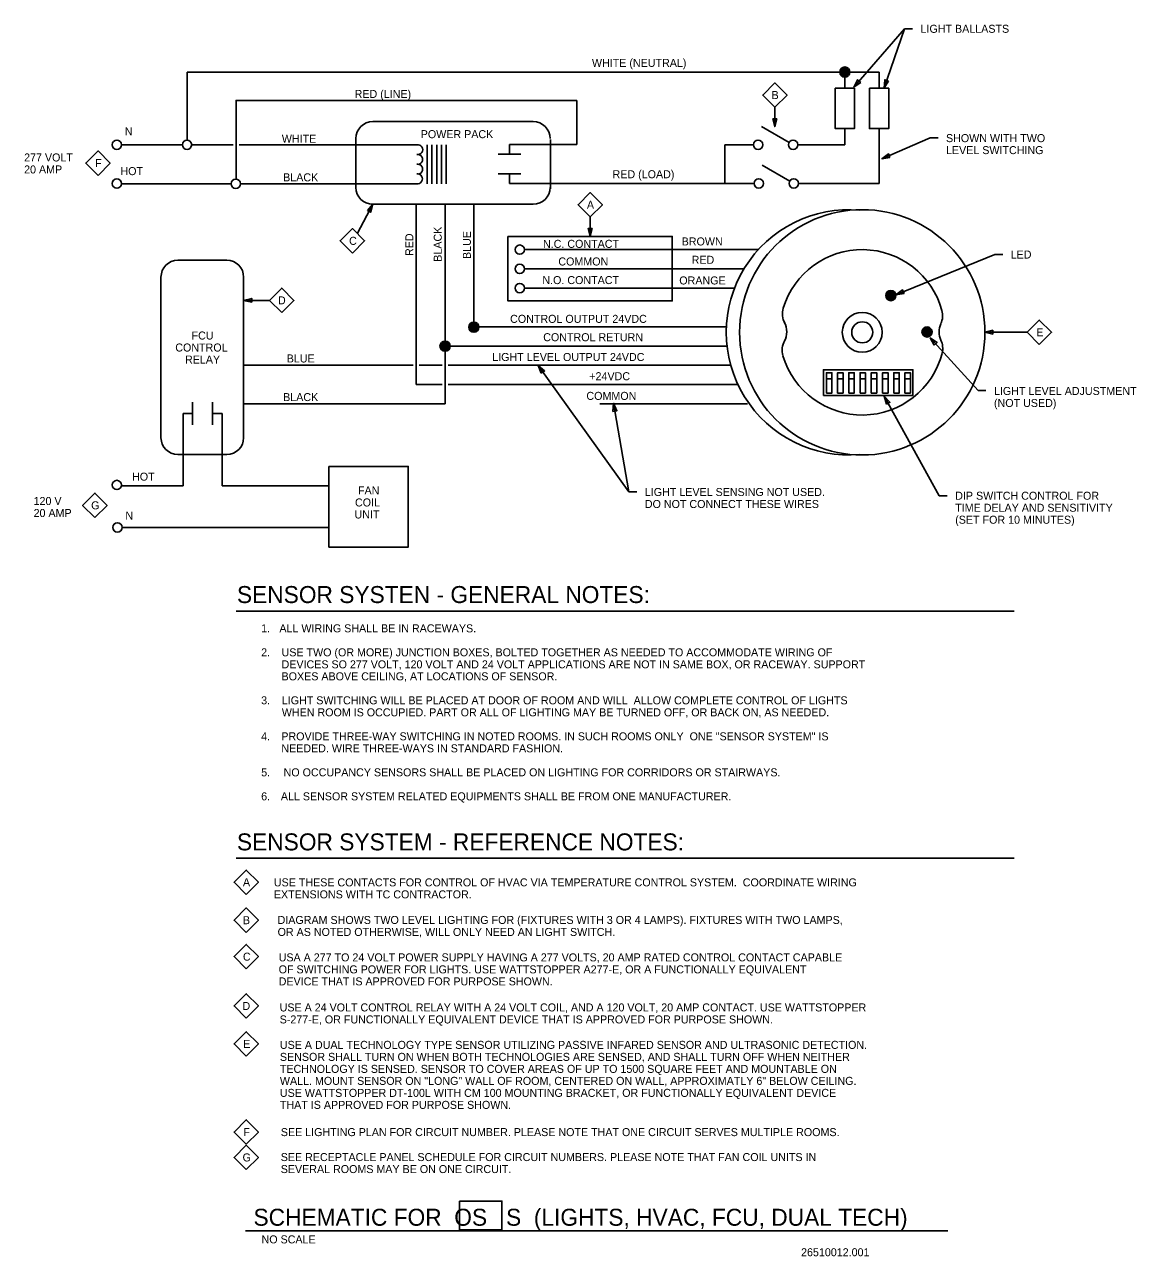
# Model space of a CAD drawing. Extents: x 10087 to 10180, y 10043 to 10146.
import ezdxf

# ---------------------------------------------------------------- set-up
doc = ezdxf.new("R2010")
doc.units = 0
for name, color, linetype in [('G-ANNO-TEXT', 7, 'Continuous'), ('G-DETL-LINE', 7, 'Continuous'), ('G-DETL-OTLN', 7, 'Continuous')]:
    doc.layers.add(name, color=color, linetype=linetype)

msp = doc.modelspace()

# ---------------------------------------------------------------- linework, layer by layer
at = {"layer": 'G-ANNO-TEXT'}
for p, q in [((10160.22, 10145.71), (10156, 10140.85)), ((10160.22, 10145.71), (10158.52, 10140.77)), ((10160.89, 10145.71), (10160.22, 10145.71)), ((10160.89, 10145.71), (10160.22, 10145.71)), ((10149.41, 10139.16), (10149.41, 10137.54)), ((10162.35, 10136.62), (10158.34, 10134.88)), ((10163.02, 10136.62), (10162.35, 10136.62)), ((10115.9, 10131.08), (10114.64, 10128.67)), ((10134.02, 10130.03), (10134.02, 10128.4)), ((10167.74, 10126.89), (10159.51, 10123.54)), ((10168.41, 10126.89), (10167.74, 10126.89)), ((10107.3, 10123.07), (10105.14, 10123.07)), ((10170.45, 10120.41), (10166.91, 10120.41)), ((10166.35, 10115.55), (10162.37, 10119.95)), ((10137.24, 10107.13), (10129.7, 10117.64)), ((10167.01, 10115.55), (10166.35, 10115.55)), ((10137.24, 10107.13), (10135.97, 10114.5)), ((10163.12, 10106.79), (10158.53, 10115.08)), ((10137.91, 10107.13), (10137.24, 10107.13)), ((10137.91, 10107.13), (10137.24, 10107.13)), ((10163.79, 10106.79), (10163.12, 10106.79)), ((10104.51, 10097.18), (10169.35, 10097.18)), ((10104.51, 10076.58), (10169.35, 10076.58)), ((10105.28, 10045.53), (10163.82, 10045.53))]:
    msp.add_line(p, q, dxfattribs=at)
for points in [[(10149.41, 10139.16), (10148.4, 10140.18), (10149.41, 10141.2), (10150.43, 10140.18)], [(10156.57, 10141.24), (10156, 10140.85), (10156.31, 10141.46)], [(10158.9, 10141.35), (10158.52, 10140.77), (10158.58, 10141.46)], [(10149.58, 10138.2), (10149.41, 10137.54), (10149.25, 10138.2)], [(10093, 10133.49), (10091.98, 10134.51), (10093, 10135.53), (10094.01, 10134.51)], [(10159.01, 10134.99), (10158.34, 10134.88), (10158.88, 10135.29)], [(10134.02, 10130.03), (10133.01, 10131.04), (10134.02, 10132.06), (10135.04, 10131.04)], [(10115.45, 10130.57), (10115.9, 10131.08), (10115.74, 10130.42)], [(10114.2, 10127.02), (10113.18, 10128.04), (10114.2, 10129.05), (10115.22, 10128.04)], [(10134.19, 10129.07), (10134.02, 10128.4), (10133.86, 10129.07)], [(10108.31, 10122.06), (10107.3, 10123.07), (10108.31, 10124.09), (10109.33, 10123.07)], [(10160.19, 10123.64), (10159.51, 10123.54), (10160.06, 10123.94)], [(10105.81, 10122.91), (10105.14, 10123.07), (10105.81, 10123.24)], [(10167.58, 10120.25), (10166.91, 10120.41), (10167.58, 10120.58)], [(10171.46, 10119.4), (10170.45, 10120.41), (10171.46, 10121.43), (10172.48, 10120.41)], [(10162.69, 10119.34), (10162.37, 10119.95), (10162.94, 10119.57)], [(10129.95, 10117), (10129.7, 10117.64), (10130.22, 10117.2)], [(10135.92, 10113.82), (10135.97, 10114.5), (10136.25, 10113.88)], [(10158.71, 10114.42), (10158.53, 10115.08), (10159, 10114.58)], [(10092.74, 10104.97), (10091.72, 10105.99), (10092.74, 10107.01), (10093.75, 10105.99)], [(10105.35, 10073.57), (10104.34, 10074.58), (10105.35, 10075.6), (10106.37, 10074.58)], [(10105.35, 10070.41), (10104.34, 10071.42), (10105.35, 10072.44), (10106.37, 10071.42)], [(10105.35, 10067.37), (10104.34, 10068.39), (10105.35, 10069.4), (10106.37, 10068.39)], [(10105.35, 10063.26), (10104.34, 10064.28), (10105.35, 10065.29), (10106.37, 10064.28)], [(10105.35, 10060.1), (10104.34, 10061.11), (10105.35, 10062.13), (10106.37, 10061.11)], [(10105.35, 10052.75), (10104.34, 10053.77), (10105.35, 10054.79), (10106.37, 10053.77)], [(10105.35, 10050.64), (10104.34, 10051.66), (10105.35, 10052.67), (10106.37, 10051.66)], [(10123.12, 10048.01), (10126.67, 10048.01), (10126.67, 10045.62), (10123.12, 10045.62)]]:
    msp.add_lwpolyline(points, close=True, dxfattribs=at)
at = {"layer": 'G-DETL-LINE'}
for p, q in [((10100.42, 10136.43), (10100.42, 10142.1)), ((10158.11, 10142.1), (10100.42, 10142.1)), ((10155.25, 10142.1), (10155.25, 10140.75)), ((10158.11, 10142.1), (10158.11, 10140.75)), ((10132.92, 10136.07), (10132.92, 10139.74)), ((10155.25, 10137.39), (10155.25, 10136.04)), ((10158.11, 10137.39), (10158.11, 10132.82)), ((10094.96, 10136.04), (10100.04, 10136.04)), ((10100.81, 10136.04), (10104.26, 10136.04)), ((10104.76, 10136.04), (10119.58, 10136.03)), ((10120.43, 10136.03), (10120.43, 10132.79)), ((10120.83, 10136.03), (10120.83, 10132.79)), ((10121.23, 10136.03), (10121.23, 10132.79)), ((10121.63, 10136.03), (10121.63, 10132.79)), ((10122.03, 10136.03), (10122.03, 10132.79)), ((10127.3, 10136.07), (10132.92, 10136.07)), ((10127.3, 10136.07), (10127.3, 10135.26)), ((10145.24, 10132.82), (10145.24, 10136.04)), ((10145.24, 10136.04), (10147.66, 10136.04)), ((10155.25, 10136.04), (10151.33, 10136.04)), ((10126.36, 10135.26), (10128.25, 10135.26)), ((10094.96, 10132.79), (10104.09, 10132.79)), ((10104.87, 10132.79), (10119.56, 10132.79)), ((10126.36, 10133.62), (10128.25, 10133.62)), ((10127.3, 10132.82), (10127.3, 10133.62)), ((10127.3, 10132.82), (10147.61, 10132.82)), ((10158.11, 10132.82), (10151.38, 10132.82)), ((10119.53, 10116.06), (10119.53, 10131.08)), ((10121.93, 10114.46), (10121.93, 10131.08)), ((10124.33, 10120.86), (10124.33, 10131.08)), ((10148.05, 10127.3), (10128.54, 10127.3)), ((10146.85, 10125.7), (10128.54, 10125.7)), ((10146.07, 10124.1), (10128.54, 10124.1)), ((10145.39, 10120.86), (10124.33, 10120.86)), ((10145.44, 10119.26), (10121.93, 10119.26)), ((10119.28, 10117.66), (10105.14, 10117.66)), ((10121.68, 10117.66), (10119.78, 10117.66)), ((10145.75, 10117.66), (10122.18, 10117.66)), ((10153.71, 10116.54), (10154.17, 10116.54)), ((10154.64, 10116.54), (10155.1, 10116.54)), ((10155.58, 10116.54), (10156.04, 10116.54)), ((10156.52, 10116.54), (10156.97, 10116.54)), ((10157.45, 10116.54), (10157.91, 10116.54)), ((10158.39, 10116.54), (10158.85, 10116.54)), ((10159.32, 10116.54), (10159.78, 10116.54)), ((10160.26, 10116.54), (10160.72, 10116.54)), ((10121.68, 10116.06), (10119.53, 10116.06)), ((10146.35, 10116.06), (10122.18, 10116.06)), ((10100.89, 10112.7), (10100.89, 10114.58)), ((10102.53, 10112.7), (10102.53, 10114.58)), ((10121.93, 10114.46), (10105.14, 10114.46)), ((10147.14, 10114.46), (10134.82, 10114.46)), ((10100.09, 10113.64), (10100.09, 10107.62)), ((10100.09, 10113.64), (10100.89, 10113.64)), ((10103.34, 10113.64), (10102.53, 10113.64)), ((10103.34, 10113.64), (10103.34, 10107.62)), ((10100.09, 10107.62), (10094.96, 10107.62)), ((10112.24, 10107.62), (10103.34, 10107.62))]:
    msp.add_line(p, q, dxfattribs=at)
for points in [[(10132.92, 10139.74), (10104.51, 10139.74), (10104.51, 10133.18)], [(10112.24, 10104.15), (10095.01, 10104.15)]]:
    msp.add_lwpolyline(points, dxfattribs=at)
for points in [[(10127.17, 10128.4), (10140.87, 10128.4), (10140.87, 10123.03), (10127.17, 10123.03)], [(10153.47, 10115.15), (10160.92, 10115.15), (10160.92, 10117.29), (10153.47, 10117.29)], [(10153.71, 10115.35), (10154.17, 10115.35), (10154.17, 10117.04), (10153.71, 10117.04)], [(10154.64, 10115.35), (10155.1, 10115.35), (10155.1, 10117.04), (10154.64, 10117.04)], [(10155.58, 10115.35), (10156.04, 10115.35), (10156.04, 10117.04), (10155.58, 10117.04)], [(10156.52, 10115.35), (10156.97, 10115.35), (10156.97, 10117.04), (10156.52, 10117.04)], [(10157.45, 10115.35), (10157.91, 10115.35), (10157.91, 10117.04), (10157.45, 10117.04)], [(10158.39, 10115.35), (10158.85, 10115.35), (10158.85, 10117.04), (10158.39, 10117.04)], [(10159.32, 10115.35), (10159.78, 10115.35), (10159.78, 10117.04), (10159.32, 10117.04)], [(10160.26, 10115.35), (10160.72, 10115.35), (10160.72, 10117.04), (10160.26, 10117.04)]]:
    msp.add_lwpolyline(points, close=True, dxfattribs=at)
for centre, radius in [((10155.25, 10142.1), 0.425), ((10155.25, 10142.1), 0.373), ((10155.25, 10142.1), 0.352), ((10155.25, 10142.1), 0.3), ((10155.25, 10142.1), 0.26), ((10155.25, 10142.1), 0.204), ((10155.25, 10142.1), 0.143), ((10155.25, 10142.1), 0.0883), ((10155.25, 10142.1), 0.0556), ((10155.25, 10142.1), 0.0519), ((10159.08, 10123.47), 0.425), ((10159.08, 10123.47), 0.373), ((10159.08, 10123.47), 0.352), ((10159.08, 10123.47), 0.3), ((10159.08, 10123.47), 0.26), ((10159.08, 10123.47), 0.204), ((10159.08, 10123.47), 0.143), ((10159.08, 10123.47), 0.0883), ((10159.08, 10123.47), 0.0556), ((10159.08, 10123.47), 0.0519), ((10156.7, 10120.41), 1.66), ((10124.33, 10120.84), 0.425), ((10124.33, 10120.84), 0.373), ((10124.33, 10120.84), 0.352), ((10124.33, 10120.84), 0.3), ((10124.33, 10120.84), 0.26), ((10124.33, 10120.84), 0.204), ((10124.33, 10120.84), 0.143), ((10124.33, 10120.84), 0.0883), ((10124.33, 10120.84), 0.0556), ((10124.33, 10120.84), 0.0519), ((10156.7, 10120.41), 0.876), ((10162.1, 10120.44), 0.425), ((10162.1, 10120.44), 0.373), ((10162.1, 10120.44), 0.352), ((10162.1, 10120.44), 0.3), ((10162.1, 10120.44), 0.26), ((10162.1, 10120.44), 0.204), ((10162.1, 10120.44), 0.143), ((10162.1, 10120.44), 0.0883), ((10162.1, 10120.44), 0.0556), ((10162.1, 10120.44), 0.0519), ((10121.93, 10119.26), 0.425), ((10121.93, 10119.26), 0.373), ((10121.93, 10119.26), 0.352), ((10121.93, 10119.26), 0.3), ((10121.93, 10119.26), 0.26), ((10121.93, 10119.26), 0.204), ((10121.93, 10119.26), 0.143), ((10121.93, 10119.26), 0.0883), ((10121.93, 10119.26), 0.0556), ((10121.93, 10119.26), 0.0519)]:
    msp.add_circle(centre, radius, dxfattribs=at)
for centre in [(10119.66, 10135.63), (10119.65, 10134.82), (10119.65, 10134.01), (10119.64, 10133.2)]:
    msp.add_ellipse(centre, major_axis=(0, 0.414), ratio=0.975779, start_param=2.929499, end_param=6.478077, dxfattribs=at)
at = {"layer": 'G-DETL-OTLN'}
for p, q in [((10150.6, 10136.23), (10148.29, 10137.57)), ((10150.66, 10133.01), (10148.35, 10134.34))]:
    msp.add_line(p, q, dxfattribs=at)
for points in [[(10154.45, 10140.75), (10156.05, 10140.75), (10156.05, 10137.39), (10154.45, 10137.39)], [(10157.3, 10140.75), (10158.91, 10140.75), (10158.91, 10137.39), (10157.3, 10137.39)], [(10112.24, 10109.23), (10118.86, 10109.23), (10118.86, 10102.52), (10112.24, 10102.52)]]:
    msp.add_lwpolyline(points, close=True, dxfattribs=at)
for points in [[(10115.9, 10137.97), (10129.28, 10137.97)], [(10114.5, 10132.48), (10114.5, 10136.57)], [(10130.71, 10136.47), (10130.71, 10132.38)], [(10129.28, 10131.08), (10115.9, 10131.08)], [(10099.65, 10126.41), (10103.74, 10126.41)], [(10098.25, 10111.63), (10098.25, 10125.01)], [(10105.14, 10125.01), (10105.14, 10111.63)], [(10103.74, 10110.23), (10099.65, 10110.23)]]:
    msp.add_lwpolyline(points, dxfattribs=at)
for centre, radius in [((10094.57, 10136.04), 0.389), ((10100.42, 10136.04), 0.389), ((10148.02, 10136.04), 0.389), ((10150.94, 10136.04), 0.389), ((10094.57, 10132.81), 0.389), ((10104.48, 10132.79), 0.389), ((10148.07, 10132.82), 0.389), ((10150.99, 10132.82), 0.389), ((10156.7, 10120.41), 10.22), ((10128.15, 10127.3), 0.389), ((10128.15, 10125.7), 0.389), ((10128.15, 10124.1), 0.389), ((10094.57, 10107.69), 0.389), ((10094.62, 10104.15), 0.389)]:
    msp.add_circle(centre, radius, dxfattribs=at)
for centre, radius, start, end in [((10115.9, 10136.57), 1.4, 90, 180), ((10129.28, 10136.57), 1.4, 0, 90), ((10115.9, 10132.48), 1.4, 180, 270), ((10129.28, 10132.48), 1.4, 270, 0), ((10155.59, 10120.41), 10.22, 84.9238, 275.0764), ((10156.7, 10120.41), 6.89, 15.2774, 163.0222), ((10099.65, 10125.01), 1.4, 90, 180), ((10103.74, 10125.01), 1.4, 0, 90), ((10151.64, 10121.96), 1.6, 163.0222, 209.9998), ((10161.8, 10121.81), 1.6, 334.9293, 15.2774), ((10148.81, 10120.45), 1.6, 330.0003, 29.9998), ((10164.7, 10120.45), 1.6, 154.9293, 205.6056), ((10151.62, 10118.92), 1.6, 150.0003, 196.4219), ((10161.81, 10119.07), 1.6, 345.2575, 25.6056), ((10156.7, 10120.41), 6.89, 196.4219, 345.2575), ((10099.65, 10111.63), 1.4, 180, 270), ((10103.74, 10111.63), 1.4, 270, 0)]:
    msp.add_arc(centre, radius, start, end, dxfattribs=at)

# ---------------------------------------------------------------- texts
at = {"layer": 'G-ANNO-TEXT'}
for s, height, p in [('LIGHT BALLASTS', 0.6667, (10161.56, 10145.37)), ('WHITE (NEUTRAL)', 0.6667, (10134.17, 10142.53)), ('RED (LINE)', 0.667, (10114.39, 10139.94)), ('B', 0.667, (10149.14, 10139.85)), ('N', 0.667, (10095.23, 10136.83)), ('WHITE', 0.667, (10108.32, 10136.21)), ('POWER PACK', 0.667, (10119.9, 10136.59)), ('SHOWN WITH TWO', 0.6667, (10163.68, 10136.26)), ('LEVEL SWITCHING', 0.6667, (10163.68, 10135.26)), ('277 VOLT', 0.667, (10086.84, 10134.65)), ('F', 0.667, (10092.76, 10134.18)), ('20 AMP', 0.667, (10086.84, 10133.65)), ('HOT', 0.667, (10094.87, 10133.51)), ('RED (LOAD)', 0.667, (10135.89, 10133.25)), ('BLACK', 0.667, (10108.43, 10132.99)), ('A', 0.667, (10133.75, 10130.71)), ('C', 0.667, (10113.93, 10127.7)), ('N.C. CONTACT', 0.6667, (10130.09, 10127.45)), ('BROWN', 0.667, (10141.65, 10127.65)), ('COMMON', 0.667, (10131.37, 10125.98)), ('RED', 0.667, (10142.48, 10126.12)), ('LED', 0.667, (10169.07, 10126.56)), ('N.O. CONTACT', 0.6667, (10130.04, 10124.43)), ('ORANGE', 0.667, (10141.45, 10124.4)), ('D', 0.667, (10108, 10122.74)), ('CONTROL OUTPUT 24VDC', 0.6667, (10127.35, 10121.2)), ('FCU', 0.667, (10100.8, 10119.81)), ('E', 0.667, (10171.21, 10120.08)), ('CONTROL', 0.667, (10099.44, 10118.81)), ('CONTROL RETURN', 0.6667, (10130.11, 10119.67)), ('RELAY', 0.667, (10100.25, 10117.81)), ('BLUE', 0.667, (10108.73, 10117.9)), ('LIGHT LEVEL OUTPUT 24VDC', 0.6667, (10125.86, 10118.02)), ('+24VDC', 0.667, (10133.95, 10116.42)), ('BLACK', 0.667, (10108.43, 10114.68)), ('COMMON', 0.667, (10133.71, 10114.78)), ('LIGHT LEVEL ADJUSTMENT', 0.6667, (10167.68, 10115.19)), ('(NOT USED)', 0.667, (10167.68, 10114.19)), ('HOT', 0.667, (10095.84, 10108.05)), ('FAN', 0.667, (10114.67, 10106.9)), ('LIGHT LEVEL SENSING NOT USED.', 0.6667, (10138.58, 10106.77)), ('DIP SWITCH CONTROL FOR ', 0.6667, (10164.45, 10106.46)), ('120 V', 0.667, (10087.63, 10106.02)), ('G', 0.667, (10092.43, 10105.66)), ('COIL', 0.667, (10114.42, 10105.9)), ('DO NOT CONNECT THESE WIRES', 0.6667, (10138.58, 10105.77)), ('TIME DELAY AND SENSITIVITY ', 0.6667, (10164.45, 10105.46)), ('20 AMP', 0.667, (10087.63, 10105.02)), ('N', 0.667, (10095.28, 10104.81)), ('UNIT', 0.667, (10114.38, 10104.9)), ('(SET FOR 10 MINUTES)', 0.6667, (10164.45, 10104.46)), ('SENSOR SYSTEN - GENERAL NOTES:', 1.4167, (10104.58, 10097.85)), ('1.', 0.667, (10106.6, 10095.41)), ('ALL WIRING SHALL BE IN RACEWAYS.', 0.6667, (10108.12, 10095.41)), ('2.', 0.667, (10106.6, 10093.41)), ('USE TWO (OR MORE) JUNCTION BOXES, BOLTED TOGETHER AS NEEDED TO ACCOMMODATE WIRING OF ', 0.6667, (10108.3, 10093.41)), ('DEVICES SO 277 VOLT, 120 VOLT AND 24 VOLT APPLICATIONS ARE NOT IN SAME BOX, OR RACEWAY. SUPPORT', 0.6667, (10108.3, 10092.41)), ('BOXES ABOVE CEILING, AT LOCATIONS OF SENSOR.', 0.6667, (10108.3, 10091.41)), ('3.', 0.667, (10106.6, 10089.41)), ('LIGHT SWITCHING WILL BE PLACED AT DOOR OF ROOM AND WILL  ALLOW COMPLETE CONTROL OF LIGHTS ', 0.6667, (10108.32, 10089.41)), ('WHEN ROOM IS OCCUPIED. PART OR ALL OF LIGHTING MAY BE TURNED OFF, OR BACK ON, AS NEEDED.', 0.6667, (10108.32, 10088.41)), ('4.', 0.667, (10106.6, 10086.41)), ('PROVIDE THREE-WAY SWITCHING IN NOTED ROOMS. IN SUCH ROOMS ONLY  ONE "SENSOR SYSTEM" IS ', 0.6667, (10108.28, 10086.41)), ('NEEDED. WIRE THREE-WAYS IN STANDARD FASHION.', 0.6667, (10108.28, 10085.41)), ('5.', 0.667, (10106.6, 10083.41)), ('NO OCCUPANCY SENSORS SHALL BE PLACED ON LIGHTING FOR CORRIDORS OR STAIRWAYS.', 0.6667, (10108.47, 10083.41)), ('6.', 0.667, (10106.6, 10081.41)), ('ALL SENSOR SYSTEM RELATED EQUIPMENTS SHALL BE FROM ONE MANUFACTURER.', 0.6667, (10108.24, 10081.41)), ('SENSOR SYSTEM - REFERENCE NOTES:', 1.4167, (10104.58, 10077.24)), ('A', 0.667, (10105.08, 10074.25)), (' USE THESE CONTACTS FOR CONTROL OF HVAC VIA TEMPERATURE CONTROL SYSTEM.  COORDINATE WIRING', 0.6667, (10107.41, 10074.24)), (' EXTENSIONS WITH TC CONTRACTOR.', 0.6667, (10107.41, 10073.24)), ('B', 0.667, (10105.08, 10071.09)), ('DIAGRAM SHOWS TWO LEVEL LIGHTING FOR (FIXTURES WITH 3 OR 4 LAMPS). FIXTURES WITH TWO LAMPS, ', 0.6667, (10107.97, 10071.11)), ('OR AS NOTED OTHERWISE, WILL ONLY NEED AN LIGHT SWITCH.', 0.6667, (10107.97, 10070.11)), ('C', 0.667, (10105.08, 10068.05)), ('USA A 277 TO 24 VOLT POWER SUPPLY HAVING A 277 VOLTS, 20 AMP RATED CONTROL CONTACT CAPABLE ', 0.6667, (10108.06, 10067.99)), ('OF SWITCHING POWER FOR LIGHTS. USE WATTSTOPPER A277-E, OR A FUNCTIONALLY EQUIVALENT', 0.6667, (10108.06, 10066.99)), ('DEVICE THAT IS APPROVED FOR PURPOSE SHOWN.', 0.6667, (10108.06, 10065.99)), ('D', 0.667, (10105.04, 10063.94)), ('USE A 24 VOLT CONTROL RELAY WITH A 24 VOLT COIL, AND A 120 VOLT, 20 AMP CONTACT. USE WATTSTOPPER', 0.6667, (10108.14, 10063.82)), ('S-277-E, OR FUNCTIONALLY EQUIVALENT DEVICE THAT IS APPROVED FOR PURPOSE SHOWN.', 0.6667, (10108.14, 10062.82)), ('E', 0.667, (10105.1, 10060.78)), ('USE A DUAL TECHNOLOGY TYPE SENSOR UTILIZING PASSIVE INFARED SENSOR AND ULTRASONIC DETECTION.', 0.6667, (10108.16, 10060.7)), ('SENSOR SHALL TURN ON WHEN BOTH TECHNOLOGIES ARE SENSED, AND SHALL TURN OFF WHEN NEITHER', 0.6667, (10108.16, 10059.7)), ('TECHNOLOGY IS SENSED. SENSOR TO COVER AREAS OF UP TO 1500 SQUARE FEET AND MOUNTABLE ON', 0.6667, (10108.16, 10058.7)), ('WALL. MOUNT SENSOR ON "LONG" WALL OF ROOM, CENTERED ON WALL, APPROXIMATLY 6" BELOW CEILING.', 0.6667, (10108.16, 10057.7)), ('USE WATTSTOPPER DT-100L WITH CM 100 MOUNTING BRACKET, OR FUNCTIONALLY EQUIVALENT DEVICE', 0.6667, (10108.16, 10056.7)), ('THAT IS APPROVED FOR PURPOSE SHOWN.', 0.6667, (10108.16, 10055.7)), ('F', 0.667, (10105.11, 10053.44)), ('SEE LIGHTING PLAN FOR CIRCUIT NUMBER. PLEASE NOTE THAT ONE CIRCUIT SERVES MULTIPLE ROOMS.', 0.6667, (10108.24, 10053.43)), ('G', 0.667, (10105.05, 10051.32)), ('SEE RECEPTACLE PANEL SCHEDULE FOR CIRCUIT NUMBERS. PLEASE NOTE THAT FAN COIL UNITS IN ', 0.6667, (10108.23, 10051.35)), ('SEVERAL ROOMS MAY BE ON ONE CIRCUIT.', 0.6667, (10108.23, 10050.35)), ('SCHEMATIC FOR  OS   S  (LIGHTS, HVAC, FCU, DUAL TECH)', 1.4167, (10105.96, 10045.96)), ('NO SCALE', 0.667, (10106.63, 10044.49)), ('26510012.001', 0.6667, (10151.6, 10043.42))]:
    msp.add_text(s, height=height, dxfattribs=at).set_placement(p)
for s, p in [('BLACK', (10121.65, 10126.29)), ('BLUE', (10124.08, 10126.52)), ('RED', (10119.28, 10126.77))]:
    msp.add_text(s, height=0.667, rotation=90, dxfattribs=at).set_placement(p)

doc.saveas('drawing.dxf')
